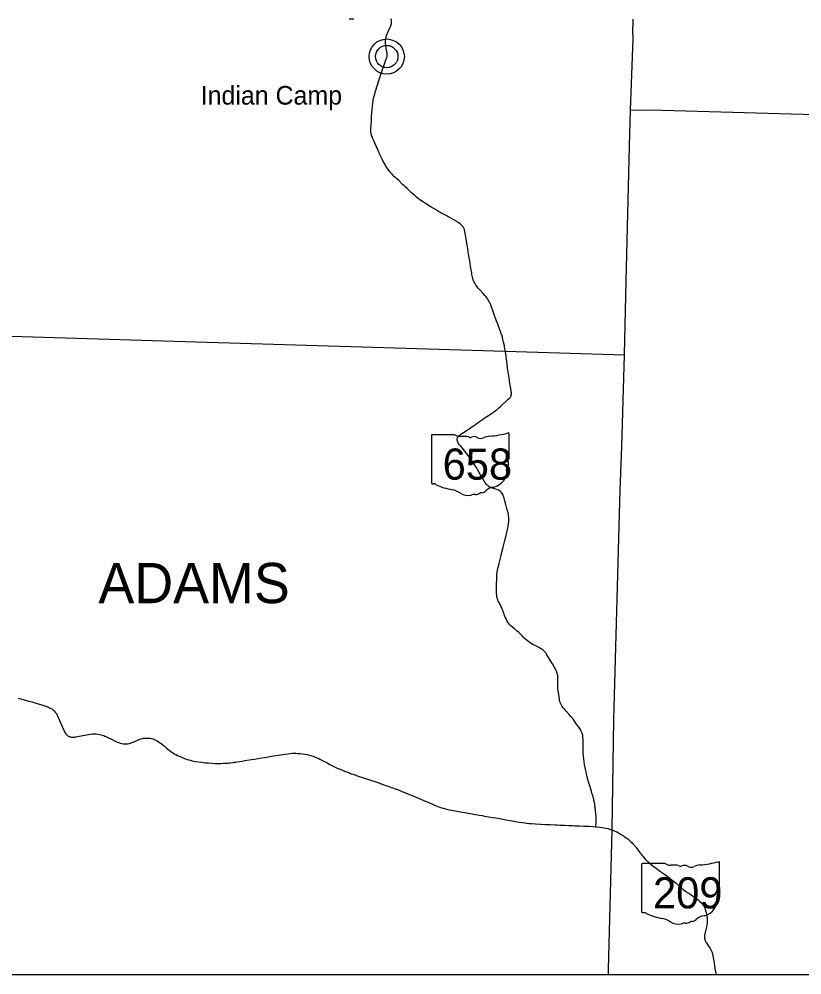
# Model space of a CAD drawing. Extents: x -12.1 to 34, y 0 to 22.
# Drawn here: x 3.691 to 6.799, y 10.977 to 14.772 of the extents above; entities that cross this region are included whole.
import ezdxf

# ---------------------------------------------------------------- set-up
doc = ezdxf.new("R2010")
doc.units = 0
for name, color, linetype in [('GM_X_State_Location', 7, 'Continuous'), ('GM_X_State_Route', 7, 'Continuous'), ('GM_X_State_Shield', 7, 'Continuous'), ('GM_X_Township', 7, 'Continuous'), ('GM_X_Township_Text', 7, 'Continuous'), ('GM_X_Unincorporated', 7, 'Continuous'), ('GM_X_Unincorporated_Location', 7, 'Continuous'), ('GM_X_Unincorporated_Text', 7, 'Continuous'), ('SH_Text', 7, 'Continuous')]:
    doc.layers.add(name, color=color, linetype=linetype)

msp = doc.modelspace()

# ---------------------------------------------------------------- linework, layer by layer
at = {"layer": 'GM_X_State_Route'}
for points in [[(5.0196, 14.7719), (5.0134, 14.7714), (5.0095, 14.7713), (5.0054, 14.7715), (5.001, 14.7721)], [(5.6212, 13.4537), (5.6205, 13.4582), (5.6196, 13.4632), (5.6183, 13.4703), (5.6175, 13.4745), (5.6146, 13.4887), (5.6119, 13.5005), (5.6096, 13.509), (5.6068, 13.5182), (5.6053, 13.5227), (5.6038, 13.5272), (5.5998, 13.5382), (5.5912, 13.5611), (5.5867, 13.5731), (5.5838, 13.5809), (5.5798, 13.5913), (5.5757, 13.6026), (5.5713, 13.6146), (5.5664, 13.6283), (5.563, 13.6369), (5.5593, 13.6454), (5.5586, 13.6468), (5.5557, 13.6528), (5.5528, 13.658), (5.5519, 13.6595), (5.5478, 13.6657), (5.5447, 13.6697), (5.5413, 13.6739), (5.5402, 13.6752), (5.5331, 13.683), (5.5199, 13.6966), (5.5128, 13.7043), (5.5094, 13.7085), (5.5082, 13.7101), (5.5054, 13.714), (5.5042, 13.7159), (5.5014, 13.7207), (5.5004, 13.7225), (5.4974, 13.7286), (5.4966, 13.7304), (5.4941, 13.7367), (5.4937, 13.7379), (5.4924, 13.742), (5.4908, 13.748), (5.4886, 13.7578), (5.4876, 13.7633), (5.4863, 13.7703), (5.4831, 13.7908), (5.4797, 13.8117), (5.4755, 13.8381), (5.4719, 13.8599), (5.4696, 13.8751), (5.4661, 13.8979), (5.4633, 13.9145), (5.4621, 13.9223), (5.4608, 13.9289), (5.4596, 13.9334), (5.4588, 13.9362), (5.4577, 13.9392), (5.4564, 13.9422), (5.4546, 13.9452), (5.4532, 13.9474), (5.4513, 13.9498), (5.4499, 13.9516), (5.4461, 13.9554), (5.4421, 13.9587), (5.4363, 13.9628), (5.4313, 13.9663), (5.4285, 13.968), (5.4166, 13.975), (5.3983, 13.985), (5.3857, 13.9919), (5.3786, 13.9958), (5.3725, 13.9991), (5.3563, 14.0082), (5.3437, 14.0155), (5.3346, 14.0208), (5.3227, 14.0281), (5.3084, 14.0371), (5.2923, 14.0476), (5.2822, 14.0545), (5.2756, 14.0595), (5.2684, 14.0653), (5.2617, 14.0711), (5.2488, 14.0828), (5.2312, 14.0989), (5.2219, 14.1077), (5.2168, 14.1124), (5.2134, 14.1156), (5.1978, 14.1305), (5.1898, 14.1381), (5.1818, 14.1458), (5.1715, 14.1561), (5.1655, 14.1625), (5.1607, 14.1684), (5.1561, 14.1745), (5.1509, 14.1822), (5.146, 14.1902), (5.1422, 14.1968), (5.1381, 14.2045), (5.1321, 14.2165), (5.1235, 14.2343), (5.1161, 14.2508), (5.1097, 14.2651), (5.1045, 14.2768), (5.1007, 14.2854), (5.0958, 14.2966), (5.0919, 14.3057), (5.0902, 14.3098), (5.0892, 14.3127), (5.088, 14.3174), (5.0876, 14.3201), (5.0874, 14.3222), (5.0871, 14.3299), (5.0875, 14.3397), (5.0882, 14.3513), (5.0893, 14.367), (5.09, 14.3775), (5.0903, 14.3838), (5.0913, 14.4013), (5.0919, 14.4106), (5.0922, 14.4147), (5.0933, 14.4251), (5.0949, 14.4385), (5.0967, 14.45), (5.0981, 14.4577), (5.1004, 14.4664), (5.106, 14.4856), (5.1203, 14.5316), (5.124, 14.5435), (5.1274, 14.5539), (5.1322, 14.5684), (5.1397, 14.59), (5.1425, 14.5981), (5.1485, 14.6139), (5.1504, 14.6199), (5.1514, 14.6244), (5.152, 14.6282), (5.1521, 14.6316), (5.152, 14.6339), (5.1515, 14.6375), (5.1497, 14.6476), (5.1469, 14.6631), (5.1462, 14.6683), (5.1456, 14.6753), (5.1453, 14.6825), (5.1456, 14.6874), (5.1458, 14.6898), (5.1463, 14.6933), (5.1476, 14.6999), (5.1497, 14.7069), (5.1524, 14.7139), (5.1564, 14.7233), (5.1642, 14.7397), (5.1664, 14.7454), (5.1677, 14.7492), (5.1682, 14.7508), (5.1691, 14.7543), (5.1694, 14.756), (5.1697, 14.7587), (5.1697, 14.7603), (5.1696, 14.7642), (5.1693, 14.767), (5.1689, 14.7689), (5.1685, 14.7704), (5.1679, 14.7724)], [(5.9811, 11.5656), (5.9811, 11.569), (5.9812, 11.5793), (5.9813, 11.5896), (5.9813, 11.5989), (5.9812, 11.6051), (5.9805, 11.6171), (5.9797, 11.6292), (5.9785, 11.6399), (5.9768, 11.652), (5.976, 11.6572), (5.9744, 11.6651), (5.9728, 11.6721), (5.9681, 11.6893), (5.9652, 11.6984), (5.9627, 11.7059), (5.9574, 11.7243), (5.9526, 11.7394), (5.949, 11.7528), (5.9451, 11.7678), (5.9416, 11.7829), (5.9392, 11.7943), (5.9362, 11.8109), (5.9339, 11.8249), (5.9324, 11.8353), (5.9312, 11.8462), (5.9305, 11.8574), (5.93, 11.8699), (5.93, 11.8897), (5.9302, 11.8991), (5.93, 11.9124), (5.9295, 11.9218), (5.9292, 11.9246), (5.9286, 11.9284), (5.9279, 11.9316), (5.9274, 11.9333), (5.9263, 11.9364), (5.9239, 11.9424), (5.9227, 11.9451), (5.9213, 11.9478), (5.919, 11.9517), (5.9169, 11.9551), (5.9118, 11.9627), (5.9017, 11.9772), (5.8915, 11.9912), (5.8817, 12.0034), (5.8752, 12.0107), (5.8628, 12.0239), (5.8555, 12.0317), (5.8501, 12.0385), (5.8472, 12.0422), (5.844, 12.0475), (5.841, 12.0537), (5.8399, 12.0563), (5.8387, 12.0598), (5.8378, 12.0628), (5.8369, 12.0669), (5.8357, 12.074), (5.8344, 12.0818), (5.8333, 12.0892), (5.833, 12.0915), (5.8311, 12.105), (5.8302, 12.1127), (5.8295, 12.1197), (5.8292, 12.1261), (5.8294, 12.1336), (5.8298, 12.1427), (5.8303, 12.1535), (5.8302, 12.1595), (5.8299, 12.1626), (5.8295, 12.1655), (5.829, 12.1685), (5.8284, 12.1711), (5.8274, 12.1742), (5.8262, 12.1774), (5.8251, 12.1802), (5.8226, 12.1856), (5.8146, 12.2005), (5.808, 12.2122), (5.7993, 12.2269), (5.7902, 12.2419), (5.7866, 12.2478), (5.7851, 12.25), (5.7814, 12.2553), (5.7793, 12.258), (5.7756, 12.2625), (5.7738, 12.264), (5.7724, 12.2652), (5.7709, 12.2665), (5.7683, 12.2685), (5.7644, 12.2711), (5.7542, 12.2771), (5.7445, 12.2824), (5.731, 12.2893), (5.7238, 12.2931), (5.7199, 12.2954), (5.7183, 12.2964), (5.7141, 12.2993), (5.7086, 12.3035), (5.7029, 12.3084), (5.6966, 12.3144), (5.689, 12.3223), (5.6806, 12.3312), (5.6749, 12.3368), (5.6688, 12.342), (5.6558, 12.3524), (5.6509, 12.3563), (5.6493, 12.3576), (5.6441, 12.3624), (5.6392, 12.3672), (5.6351, 12.3721), (5.6312, 12.3779), (5.6275, 12.384), (5.6242, 12.3904), (5.6208, 12.3979), (5.6185, 12.4038), (5.6165, 12.4091), (5.6131, 12.4194), (5.6105, 12.4264), (5.6082, 12.4321), (5.605, 12.4387), (5.5961, 12.4557), (5.5934, 12.4616), (5.5911, 12.4669), (5.5893, 12.4723), (5.5877, 12.4786), (5.5869, 12.4848), (5.5864, 12.4916), (5.5861, 12.5017), (5.5861, 12.5156), (5.5865, 12.5296), (5.587, 12.5465), (5.5875, 12.5605), (5.5881, 12.5685), (5.5889, 12.5754), (5.5902, 12.584), (5.5927, 12.5958), (5.5966, 12.6112), (5.6029, 12.6371), (5.6071, 12.6552), (5.6123, 12.6759), (5.6192, 12.7022), (5.6243, 12.722), (5.6286, 12.7407), (5.6308, 12.7511), (5.6324, 12.7593), (5.634, 12.7699), (5.6346, 12.7775), (5.635, 12.7852), (5.6348, 12.792), (5.6347, 12.7943), (5.6341, 12.8002), (5.6337, 12.8033), (5.6332, 12.8066), (5.6323, 12.8112), (5.6291, 12.8238), (5.6236, 12.8447), (5.6196, 12.8596), (5.6167, 12.8694), (5.6131, 12.88), (5.6114, 12.8843), (5.6093, 12.888), (5.6077, 12.8904), (5.6047, 12.8939), (5.6016, 12.8969), (5.5986, 12.899), (5.5942, 12.9014), (5.5895, 12.9033), (5.5829, 12.9056), (5.5686, 12.91), (5.5631, 12.9122), (5.5607, 12.9132), (5.5568, 12.9153), (5.5539, 12.9173), (5.5502, 12.9201), (5.5463, 12.9241), (5.5433, 12.9279), (5.5399, 12.9326), (5.5369, 12.9375), (5.5278, 12.9541), (5.523, 12.9625), (5.516, 12.9749), (5.5109, 12.9838), (5.5062, 12.9914), (5.5021, 12.9984), (5.4975, 13.0056), (5.4901, 13.0163), (5.4776, 13.0336), (5.469, 13.0458), (5.4594, 13.0582), (5.4524, 13.0668), (5.4426, 13.0783), (5.4395, 13.0818), (5.4355, 13.0874), (5.4336, 13.0902), (5.4321, 13.0932), (5.4314, 13.0949), (5.4308, 13.0967), (5.4302, 13.0993), (5.4301, 13.1013), (5.4301, 13.1032), (5.4304, 13.106), (5.4313, 13.1088), (5.4328, 13.1116), (5.4344, 13.1143), (5.4368, 13.1171), (5.4394, 13.1197), (5.4435, 13.1229), (5.4491, 13.1268), (5.4555, 13.131), (5.4618, 13.135), (5.4675, 13.1389), (5.4716, 13.1415), (5.4758, 13.1445), (5.4831, 13.1493), (5.4898, 13.1539), (5.4931, 13.1562), (5.4972, 13.1591), (5.5092, 13.1672), (5.5153, 13.1717), (5.5225, 13.1766), (5.5266, 13.1795), (5.5303, 13.1822), (5.5326, 13.1837), (5.5363, 13.1861), (5.5418, 13.1898), (5.5477, 13.1937), (5.5549, 13.1982), (5.5663, 13.2056), (5.5743, 13.211), (5.5812, 13.2161), (5.5886, 13.2219), (5.5945, 13.227), (5.6008, 13.2325), (5.6069, 13.2388), (5.6256, 13.2569), (5.6325, 13.263), (5.6389, 13.2687), (5.6414, 13.2715), (5.6429, 13.2737), (5.6442, 13.2768), (5.6449, 13.2798), (5.6451, 13.281), (5.6453, 13.2823), (5.6455, 13.285), (5.6454, 13.2868), (5.6453, 13.2888), (5.6449, 13.2918), (5.6444, 13.2957), (5.6438, 13.2984), (5.6434, 13.301), (5.6427, 13.3046), (5.6424, 13.3068), (5.6414, 13.3124), (5.6408, 13.3162), (5.6402, 13.3202), (5.6395, 13.3247), (5.6379, 13.3365), (5.6365, 13.3464), (5.6352, 13.3545), (5.634, 13.3629), (5.6318, 13.3777), (5.6289, 13.3986), (5.627, 13.4123), (5.6253, 13.4251), (5.6243, 13.4328), (5.623, 13.4415), (5.6214, 13.4523), (5.6212, 13.4537)], [(3.6874, 12.0764), (3.6981, 12.0731), (3.711, 12.0695), (3.7239, 12.0659), (3.7407, 12.0612), (3.7417, 12.0609), (3.7631, 12.0546), (3.7848, 12.0479), (3.7968, 12.0438), (3.8042, 12.0409), (3.8085, 12.0394), (3.8113, 12.0382), (3.8171, 12.0353), (3.8209, 12.0331), (3.8236, 12.0313), (3.8274, 12.0282), (3.8299, 12.0256), (3.8332, 12.0217), (3.8361, 12.0178), (3.8377, 12.0154), (3.8399, 12.0117), (3.8429, 12.006), (3.8484, 11.9945), (3.8517, 11.9871), (3.8574, 11.9731), (3.8627, 11.9605), (3.8648, 11.9557), (3.8667, 11.951), (3.8679, 11.9485), (3.871, 11.9427), (3.8734, 11.9386), (3.876, 11.9347), (3.8779, 11.9322), (3.8797, 11.9302), (3.8811, 11.929), (3.8848, 11.9263), (3.8864, 11.9251), (3.8884, 11.924), (3.8903, 11.9231), (3.8933, 11.9221), (3.8976, 11.9212), (3.9022, 11.9207), (3.9061, 11.9207), (3.9086, 11.9209), (3.9127, 11.9214), (3.9154, 11.9218), (3.9225, 11.9231), (3.9432, 11.9276), (3.9596, 11.9308), (3.9666, 11.9321), (3.9729, 11.9332), (3.9796, 11.934), (3.9829, 11.9343), (3.9874, 11.9344), (3.9919, 11.9344), (3.9969, 11.9342), (4.0024, 11.9336), (4.0096, 11.9323), (4.0161, 11.9308), (4.0224, 11.929), (4.0277, 11.9271), (4.0313, 11.9256), (4.0355, 11.9237), (4.0404, 11.9214), (4.046, 11.9188), (4.0605, 11.9113), (4.0717, 11.9053), (4.0809, 11.9012), (4.0861, 11.8993), (4.0889, 11.8984), (4.092, 11.8974), (4.0983, 11.896), (4.1042, 11.8951), (4.1094, 11.8947), (4.1148, 11.8946), (4.1224, 11.8953), (4.1284, 11.8963), (4.1332, 11.8977), (4.1399, 11.9002), (4.1497, 11.9043), (4.1576, 11.9079), (4.1661, 11.9113), (4.1743, 11.9141), (4.1809, 11.9158), (4.1846, 11.9166), (4.188, 11.9171), (4.1918, 11.9175), (4.1984, 11.9177), (4.2036, 11.9174), (4.2095, 11.9168), (4.215, 11.9159), (4.2211, 11.9142), (4.2265, 11.9124), (4.2308, 11.9106), (4.2365, 11.9078), (4.2425, 11.9043), (4.2487, 11.9002), (4.2547, 11.8956), (4.2662, 11.8861), (4.2763, 11.8778), (4.2864, 11.8694), (4.2937, 11.8639), (4.3008, 11.8593), (4.3034, 11.8577), (4.312, 11.8529), (4.3143, 11.8517), (4.32, 11.8487), (4.3263, 11.8457), (4.3295, 11.8444), (4.3332, 11.8427), (4.3449, 11.8377), (4.3541, 11.8343), (4.3632, 11.8315), (4.3714, 11.8292), (4.3745, 11.8284), (4.3848, 11.8262), (4.3911, 11.825), (4.4164, 11.8214), (4.4292, 11.8198), (4.443, 11.8186), (4.4567, 11.8176), (4.4689, 11.8172), (4.4741, 11.8171), (4.477, 11.8171), (4.4825, 11.8169), (4.488, 11.817), (4.4929, 11.8171), (4.5008, 11.8174), (4.5135, 11.8181), (4.5193, 11.8185), (4.5246, 11.8191), (4.53, 11.8197), (4.5412, 11.8209), (4.5446, 11.8214), (4.5496, 11.8221), (4.557, 11.8232), (4.5669, 11.8247), (4.5767, 11.8263), (4.5867, 11.8279), (4.6045, 11.8308), (4.6135, 11.8321), (4.626, 11.834), (4.6316, 11.835), (4.6401, 11.8363), (4.6551, 11.8384), (4.666, 11.8401), (4.6798, 11.8427), (4.7003, 11.8465), (4.721, 11.8498), (4.7457, 11.8537), (4.759, 11.8553), (4.7688, 11.8565), (4.7757, 11.8571), (4.7803, 11.8573), (4.7899, 11.8572), (4.7989, 11.8568), (4.8064, 11.8564), (4.815, 11.8554), (4.8249, 11.8539), (4.8342, 11.8521), (4.8437, 11.8497), (4.8524, 11.8472), (4.858, 11.8452), (4.8632, 11.8433), (4.8722, 11.8395), (4.8804, 11.8358), (4.8846, 11.8338), (4.8924, 11.83), (4.9017, 11.8251), (4.9089, 11.8214), (4.9135, 11.8189), (4.9244, 11.8132), (4.9347, 11.8079), (4.9405, 11.8051), (4.9484, 11.8012), (4.9542, 11.7985), (4.9579, 11.7969), (4.9611, 11.7954), (4.9648, 11.7938), (4.968, 11.7924), (4.9772, 11.7886), (4.982, 11.7867), (4.9869, 11.7847), (4.9951, 11.7816), (5.0022, 11.7791), (5.0071, 11.7773), (5.0238, 11.7714), (5.0406, 11.7656), (5.0502, 11.7621), (5.0615, 11.7584), (5.0735, 11.7546), (5.1184, 11.7393), (5.1354, 11.7336), (5.1582, 11.7257), (5.1629, 11.724), (5.1686, 11.7219), (5.1751, 11.7195), (5.1795, 11.7179), (5.1865, 11.7152), (5.1893, 11.7142), (5.1969, 11.7114), (5.2018, 11.7095), (5.211, 11.7059), (5.2207, 11.702), (5.2518, 11.6889), (5.2786, 11.6777), (5.2973, 11.6697), (5.3288, 11.656), (5.3401, 11.6512), (5.351, 11.647), (5.3642, 11.6423), (5.3747, 11.6388), (5.3843, 11.6362), (5.3997, 11.6328), (5.4151, 11.6296), (5.4305, 11.6268), (5.4506, 11.6234), (5.4889, 11.6168), (5.4964, 11.6156), (5.517, 11.6119), (5.529, 11.6097), (5.5382, 11.608), (5.5554, 11.6052), (5.5703, 11.6026), (5.5835, 11.6002), (5.6054, 11.5964), (5.6237, 11.5931), (5.6403, 11.5899), (5.6569, 11.587), (5.6587, 11.5867), (5.6765, 11.5838), (5.688, 11.5821), (5.6996, 11.5806), (5.7054, 11.5799), (5.7152, 11.5788), (5.7256, 11.5777), (5.7408, 11.5765), (5.7611, 11.5754), (5.7809, 11.5747), (5.7995, 11.5741), (5.8158, 11.5733), (5.8268, 11.5728), (5.8379, 11.5723), (5.8559, 11.5715), (5.8722, 11.5706), (5.8827, 11.5701), (5.8885, 11.5699), (5.8965, 11.5697), (5.9148, 11.569), (5.9333, 11.5682), (5.9443, 11.5678), (5.9542, 11.5674), (5.9716, 11.5664), (5.9811, 11.5656), (5.9849, 11.5653), (6.0057, 11.5629), (6.0126, 11.5617), (6.0199, 11.5602), (6.0278, 11.558), (6.0394, 11.5544), (6.0456, 11.5523)], [(6.0456, 11.5523), (6.0482, 11.5514), (6.0557, 11.5483), (6.0636, 11.5447), (6.0708, 11.541), (6.079, 11.5365), (6.09, 11.5297), (6.0933, 11.5273), (6.1005, 11.5219), (6.1088, 11.5155), (6.1146, 11.5107), (6.1186, 11.5071), (6.1219, 11.5041), (6.1254, 11.5007), (6.1284, 11.4976), (6.1308, 11.495), (6.133, 11.4924), (6.135, 11.4902), (6.1371, 11.4874), (6.1403, 11.4833), (6.1542, 11.4648), (6.1581, 11.4594), (6.1615, 11.455), (6.1649, 11.4508), (6.1679, 11.4471), (6.1714, 11.4432), (6.1741, 11.4402), (6.1769, 11.4372), (6.1794, 11.4346), (6.1823, 11.4318), (6.1855, 11.4286), (6.1895, 11.425), (6.1984, 11.4174), (6.2075, 11.41), (6.22, 11.4005), (6.2272, 11.3951), (6.2339, 11.3901), (6.2456, 11.3819), (6.2624, 11.37), (6.2776, 11.3589), (6.2891, 11.35), (6.2995, 11.3415), (6.316, 11.3268), (6.3275, 11.3169), (6.3317, 11.3136), (6.3364, 11.3102), (6.3446, 11.3046), (6.3538, 11.2985), (6.3639, 11.2917), (6.3758, 11.2833), (6.38, 11.2802), (6.3868, 11.2747), (6.3898, 11.272), (6.3933, 11.2689), (6.3982, 11.2641), (6.4002, 11.2619), (6.4024, 11.2593), (6.406, 11.2548), (6.4077, 11.2522), (6.4094, 11.2495), (6.4106, 11.2473), (6.4116, 11.2451), (6.4128, 11.2423), (6.414, 11.2394), (6.4149, 11.2366), (6.4159, 11.2333), (6.4182, 11.2249), (6.4194, 11.2198), (6.4206, 11.2146), (6.4214, 11.2101), (6.4219, 11.2075), (6.4224, 11.2043), (6.4227, 11.202), (6.4229, 11.1999), (6.423, 11.1975), (6.4231, 11.1942), (6.4231, 11.1905), (6.4229, 11.1877), (6.4224, 11.1839), (6.422, 11.1807), (6.4212, 11.1761), (6.4196, 11.1687), (6.4169, 11.1569), (6.4154, 11.1509), (6.4142, 11.1451), (6.4135, 11.1414), (6.4128, 11.1375), (6.4125, 11.1349), (6.4123, 11.1328), (6.4121, 11.1307), (6.4121, 11.1288), (6.4121, 11.1274), (6.4122, 11.1257), (6.4123, 11.1247), (6.4125, 11.1235), (6.4126, 11.1223), (6.4128, 11.121), (6.4132, 11.1191), (6.4138, 11.117), (6.4146, 11.1143), (6.4152, 11.1126), (6.4158, 11.1111), (6.4165, 11.1094), (6.4172, 11.1082), (6.4179, 11.1068), (6.4195, 11.1042), (6.4236, 11.0982), (6.4263, 11.0944), (6.4296, 11.0896), (6.432, 11.0861), (6.4341, 11.0827), (6.4359, 11.0797), (6.4367, 11.078), (6.4377, 11.076), (6.4387, 11.074), (6.4397, 11.0717), (6.4407, 11.0691), (6.4419, 11.0656), (6.4431, 11.0621), (6.4441, 11.0586), (6.4449, 11.0551), (6.4457, 11.0515), (6.4463, 11.0482), (6.4468, 11.0448), (6.4485, 11.0335), (6.45, 11.0227), (6.4512, 11.0147), (6.4533, 11.0021), (6.4546, 10.9952), (6.4569, 10.985), (6.4589, 10.9773)]]:
    msp.add_lwpolyline(points, dxfattribs=at)
at = {"layer": 'GM_X_State_Shield'}
for p, q in [((5.3277, 13.1179), (5.3277, 12.9303)), ((5.4212, 13.1212), (5.3307, 13.1212)), ((5.6367, 13.0277), (5.6367, 13.1258)), ((5.6366, 13.0277), (5.6367, 13.0277)), ((6.4712, 11.3255), (6.4712, 11.4236)), ((6.1622, 11.4157), (6.1622, 11.2281)), ((6.2557, 11.419), (6.1652, 11.419)), ((6.4711, 11.3255), (6.4712, 11.3255))]:
    msp.add_line(p, q, dxfattribs=at)
for centre, major_axis, start_param, end_param in [((5.3312, 13.1183), (0.00358, 0), 1.712693, 3.28349), ((5.4427, 13.1429), (0.0347, 0), 4.042523, 4.731795), ((5.4543, 13.0158), (0.1246, 0), 1.404758, 1.657858), ((5.4826, 13.1193), (0.01, 0), 3.836095, 5.185415), ((5.4973, 13.0976), (0.0208, 0), 0.950623, 2.079405), ((5.5241, 13.1274), (0.0251, 0), 4.081561, 5.145723), ((5.5684, 13.0639), (0.0659, 0), 1.699011, 2.107814), ((5.5266, 13.3769), (0.3277, 0), 4.814394, 5.042369), ((5.6332, 13.1262), (0.00344, 0), 6.141152, 7.989035), ((5.6359, 13.0205), (0.00532, 0), 1.883978, 3.671073), ((5.602, 13.0081), (0.032, 0), 5.934695, 6.695948), ((5.633, 13.0273), (0.00368, 0), 5.05454, 6.418171), ((5.5449, 12.9741), (0.082, 0), 5.101752, 6.440018), ((5.649, 12.9866), (0.0232, 0), 2.387724, 3.262537), ((5.3312, 12.9299), (0.00361, 0), 3.00124, 4.508301), ((5.3318, 12.9491), (0.0276, 0), 4.665946, 4.897461), ((5.3374, 12.9195), (0.00994, 0), 0.519207, 1.627899), ((5.4629, 13.0881), (0.2366, 0), 4.195997, 4.488961), ((5.3923, 12.846), (0.074, 0), 0.823519, 1.323587), ((5.5795, 12.8776), (0.0449, 0), 1.647645, 2.488434), ((5.4724, 12.9186), (0.047, 0), 4.026481, 4.996735), ((5.4996, 12.8537), (0.0386, 0), 1.495662, 1.94098), ((5.503, 12.9045), (0.025, 0), 4.691044, 5.507374), ((5.5256, 12.8863), (0.00705, 0), 1.147584, 2.315152), ((5.5226, 12.9121), (0.0265, 0), 4.937069, 5.64225), ((6.3611, 11.6747), (0.3277, 0), 4.814394, 5.042369), ((6.4677, 11.424), (0.00344, 0), 6.141152, 7.989035), ((6.1657, 11.4161), (0.00358, 0), 1.712693, 3.28349), ((6.2773, 11.4407), (0.0347, 0), 4.042523, 4.731795), ((6.2888, 11.3136), (0.1246, 0), 1.404758, 1.657858), ((6.3171, 11.4171), (0.01, 0), 3.836095, 5.185415), ((6.3318, 11.3954), (0.0208, 0), 0.950623, 2.079405), ((6.3587, 11.4252), (0.0251, 0), 4.081561, 5.145723), ((6.4029, 11.3617), (0.0659, 0), 1.699011, 2.107814), ((6.4704, 11.3183), (0.00532, 0), 1.883978, 3.671073), ((6.4365, 11.3059), (0.032, 0), 5.934695, 6.695948), ((6.4675, 11.3251), (0.00368, 0), 5.05454, 6.418171), ((6.3795, 11.2719), (0.082, 0), 5.101752, 6.440018), ((6.4835, 11.2844), (0.0232, 0), 2.387724, 3.262537), ((6.1658, 11.2277), (0.00361, 0), 3.00124, 4.508301), ((6.1663, 11.2469), (0.0276, 0), 4.665946, 4.897461), ((6.1719, 11.2173), (0.00994, 0), 0.519207, 1.627899), ((6.2974, 11.3859), (0.2366, 0), 4.195997, 4.488961), ((6.2269, 11.1438), (0.074, 0), 0.823519, 1.323587), ((6.3571, 11.2099), (0.0265, 0), 4.937069, 5.64225), ((6.414, 11.1754), (0.0449, 0), 1.647645, 2.488434), ((6.3069, 11.2164), (0.047, 0), 4.026481, 4.996735), ((6.3341, 11.1515), (0.0386, 0), 1.495662, 1.94098), ((6.3375, 11.2023), (0.025, 0), 4.691044, 5.507374), ((6.3601, 11.1841), (0.00705, 0), 1.147584, 2.315152)]:
    msp.add_ellipse(centre, major_axis=major_axis, ratio=0.8, start_param=start_param, end_param=end_param, dxfattribs=at)
at = {"layer": 'GM_X_Township'}
for points in [[(6.1181, 14.4109), (6.1294, 14.6938), (6.1292, 14.7027), (6.1291, 14.7048), (6.1288, 14.7079), (6.1284, 14.7092), (6.1278, 14.7108), (6.1271, 14.712), (6.1285, 14.7719)], [(6.0303, 10.9773), (6.0309, 10.9988), (6.0454, 11.5528), (6.0514, 11.9907), (6.0776, 12.9011), (6.0839, 13.075), (6.0948, 13.439), (6.101, 13.7314), (6.114, 14.2676), (6.1181, 14.4109), (6.197, 14.4116), (7.1288, 14.3854)], [(2.8817, 13.5392), (3.0915, 13.5317), (3.5107, 13.5177), (3.513, 13.5176), (3.5238, 13.517), (3.5287, 13.5169), (4.3507, 13.4926), (5.621, 13.4542), (6.0948, 13.439)]]:
    msp.add_lwpolyline(points, dxfattribs=at)
at = {"layer": 'GM_X_Unincorporated'}
for radius in [0.0698, 0.0442]:
    msp.add_circle((5.1505, 14.6232), radius, dxfattribs=at)
at = {"layer": 'GM_X_Unincorporated_Location'}
msp.add_line((5.1505, 14.6232), (5.1505, 14.6232), dxfattribs=at)
at = {"layer": 'SH_Text'}
msp.add_lwpolyline([(2.8817, 20.3063), (10.5897, 20.3063), (10.5897, 10.9773), (2.8817, 10.9773)], close=True, dxfattribs=at)

# ---------------------------------------------------------------- texts
at = {"layer": 'GM_X_State_Location'}
msp.add_text('658', height=0.000178, rotation=0, dxfattribs=at).set_placement((5.4253, 12.9872))
for s in ['s', 'r']:
    msp.add_text(s, height=0.000178, dxfattribs=at).set_placement((5.4879, 13.0002))
at = {"layer": 'GM_X_State_Shield'}
for s, p in [('658', (5.3723, 12.9435)), ('209', (6.2076, 11.2413))]:
    msp.add_text(s, height=0.1236, dxfattribs=at).set_placement(p)
at = {"layer": 'GM_X_Township_Text'}
msp.add_text('ADAMS', height=0.1598, rotation=0, dxfattribs=at).set_placement((4.0056, 12.4531))
at = {"layer": 'GM_X_Unincorporated_Text'}
msp.add_text('Indian Camp', height=0.074041, rotation=0, dxfattribs=at).set_placement((4.4117, 14.4324))

doc.saveas('drawing.dxf')
